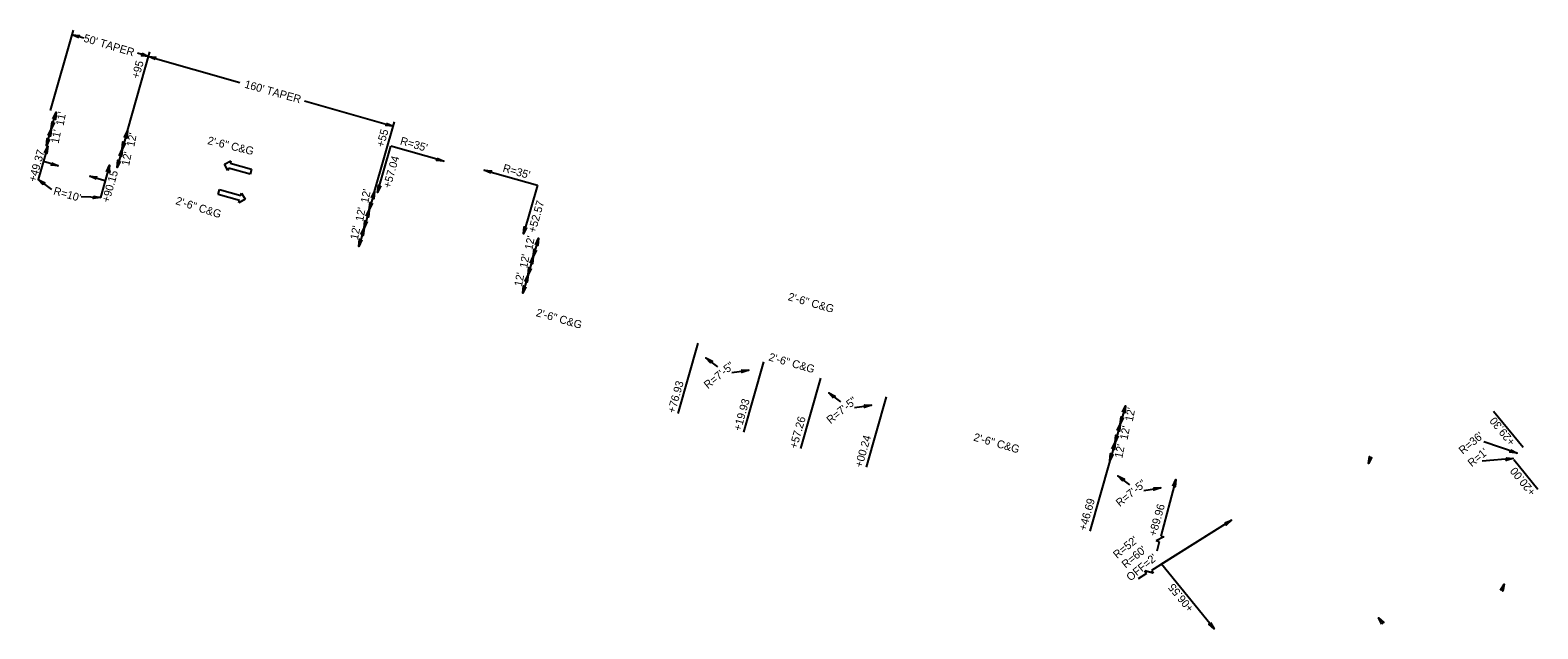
# Model space of a CAD drawing. Extents: x 2320991 to 2332664, y 598057 to 612602.
# Drawn here: x 2320991 to 2321940, y 598099 to 598475 of the extents above; entities that cross this region are included whole.
import ezdxf

# ---------------------------------------------------------------- set-up
doc = ezdxf.new("R2010")
doc.units = 0
for name, color, linetype in [('Prop Dimension', 7, 'Continuous'), ('Prop Dimension Text', 7, 'Continuous'), ('Prop Lane Arrow CELL', 7, 'Continuous'), ('Prop Terminator CELL', 7, 'Continuous')]:
    doc.layers.add(name, color=color, linetype=linetype)

msp = doc.modelspace()

# ---------------------------------------------------------------- linework, layer by layer
at = {"layer": 'Prop Dimension'}
for p, q in [((2321003.74, 598424.65), (2321018.17, 598475.28)), ((2321024.74, 598470.34), (2321017.37, 598472.44)), ((2321052.1, 598411.9), (2321066.26, 598461.58)), ((2321065.45, 598458.74), (2321058.32, 598460.77)), ((2321065.45, 598458.74), (2321122.9, 598442.36)), ((2321163.64, 598430.75), (2321219.32, 598414.87)), ((2321004.16, 598413.12), (2321007.18, 598423.7)), ((2321001.14, 598402.52), (2321004.15, 598413.09)), ((2321052.1, 598411.9), (2321048.81, 598400.36)), ((2321207.61, 598373.81), (2321220.13, 598417.71)), ((2321001.89, 598402.21), (2320995.93, 598381.3)), ((2321048.81, 598400.36), (2321045.52, 598388.82)), ((2321209.58, 598373.25), (2321217.88, 598402.37)), ((2321251.23, 598392.86), (2321217.88, 598402.37)), ((2321008.57, 598389.91), (2320999.15, 598392.6)), ((2321040.89, 598390.25), (2321035.12, 598370)), ((2320995.93, 598381.3), (2321004.19, 598375.07)), ((2321028.34, 598383.43), (2321038.15, 598380.63)), ((2321276.65, 598387.22), (2321310.17, 598377.66)), ((2321207.61, 598373.81), (2321204.33, 598362.27)), ((2321310.17, 598377.66), (2321301.45, 598347.06)), ((2321035.12, 598370), (2321023.02, 598370.34)), ((2321204.33, 598362.27), (2321201.04, 598350.73)), ((2321201.04, 598350.73), (2321197.75, 598339.19)), ((2321310.88, 598344.38), (2321307.59, 598332.84)), ((2321307.59, 598332.84), (2321304.3, 598321.3)), ((2321304.3, 598321.3), (2321301.01, 598309.75)), ((2321411.18, 598278.35), (2321398.57, 598234.11)), ((2321423.89, 598263.36), (2321416.33, 598269.08)), ((2321452.53, 598266.56), (2321439.92, 598222.32)), ((2321432.63, 598259.88), (2321443.26, 598261.41)), ((2321488.43, 598256.33), (2321475.82, 598212.09)), ((2321501.14, 598241.34), (2321493.58, 598247.06)), ((2321509.88, 598237.86), (2321520.51, 598239.39)), ((2321529.76, 598244.55), (2321517.15, 598200.31)), ((2321680.47, 598239.02), (2321677.18, 598227.48)), ((2321930.74, 598212.66), (2321912.13, 598235.45)), ((2321677.18, 598227.48), (2321673.89, 598215.94)), ((2321673.89, 598215.94), (2321670.6, 598204.4)), ((2321926.93, 598209.06), (2321906.05, 598216.36)), ((2321670.6, 598204.4), (2321657.99, 598160.16)), ((2321924.57, 598205.85), (2321905.07, 598204.03)), ((2321924.87, 598205.14), (2321940.05, 598186.55)), ((2321683.26, 598189.21), (2321675.7, 598194.93)), ((2321712.2, 598192.53), (2321702.66, 598156.92)), ((2321691.99, 598185.73), (2321702.63, 598187.26)), ((2321747.18, 598166.97), (2321696.71, 598135.39)), ((2321747.18, 598166.97), (2321702.69, 598139.13)), ((2321701.73, 598153.43), (2321700.11, 598147.38)), ((2321693.65, 598133.47), (2321688.34, 598130.15)), ((2321736.29, 598098.62), (2321703.04, 598139.35))]:
    msp.add_line(p, q, dxfattribs=at)
at = {"layer": 'Prop Dimension Text'}
for p, q in [((2321704.59, 598156.4), (2321699.79, 598153.95)), ((2321701.73, 598153.43), (2321699.79, 598153.95)), ((2321702.66, 598156.92), (2321704.59, 598156.4)), ((2321693.65, 598133.47), (2321692.58, 598135.17)), ((2321697.77, 598133.69), (2321692.58, 598135.17)), ((2321696.71, 598135.39), (2321697.77, 598133.69))]:
    msp.add_line(p, q, dxfattribs=at)
at = {"layer": 'Prop Lane Arrow CELL'}
for p, q in [((2321113.22, 598390.88), (2321117.13, 598393.1)), ((2321115.4, 598387.04), (2321113.22, 598390.88)), ((2321117.13, 598393.1), (2321116.72, 598391.65)), ((2321116.72, 598391.65), (2321130.18, 598387.82)), ((2321115.81, 598388.48), (2321115.4, 598387.04)), ((2321129.28, 598384.64), (2321115.81, 598388.48)), ((2321130.18, 598387.82), (2321129.28, 598384.64)), ((2321109.16, 598371.96), (2321110.07, 598375.14)), ((2321122.63, 598368.13), (2321109.16, 598371.96)), ((2321110.07, 598375.14), (2321123.53, 598371.3)), ((2321123.53, 598371.3), (2321123.94, 598372.74)), ((2321123.94, 598372.74), (2321126.12, 598368.9)), ((2321126.12, 598368.9), (2321122.22, 598366.68)), ((2321122.22, 598366.68), (2321122.63, 598368.13))]:
    msp.add_line(p, q, dxfattribs=at)
at = {"layer": 'Prop Terminator CELL'}
for points in [[(2321021.48, 598470.46), (2321017.37, 598472.44), (2321021.94, 598471.97), (2321021.16, 598471.36)], [(2321061.33, 598460.72), (2321065.45, 598458.74), (2321060.88, 598459.21), (2321061.65, 598459.82)], [(2321069.56, 598456.76), (2321065.45, 598458.74), (2321070.02, 598458.27), (2321069.25, 598457.65)], [(2321005.2, 598419.59), (2321007.18, 598423.7), (2321006.7, 598419.13), (2321006.09, 598419.9)], [(2321002.17, 598408.98), (2321004.15, 598413.09), (2321003.68, 598408.52), (2321003.07, 598409.3)], [(2321006.14, 598417.24), (2321004.16, 598413.12), (2321004.63, 598417.69), (2321005.24, 598416.92)], [(2321050.12, 598407.79), (2321052.1, 598411.9), (2321051.63, 598407.33), (2321051.02, 598408.11)], [(2321215.2, 598416.85), (2321219.32, 598414.87), (2321214.75, 598415.35), (2321215.52, 598415.96)], [(2320999.91, 598398.1), (2321001.89, 598402.21), (2321001.42, 598397.64), (2321000.8, 598398.41)], [(2321003.11, 598406.63), (2321001.14, 598402.52), (2321001.61, 598407.09), (2321002.22, 598406.31)], [(2321046.83, 598396.25), (2321048.81, 598400.36), (2321048.34, 598395.79), (2321047.73, 598396.57)], [(2321050.79, 598404.48), (2321048.81, 598400.36), (2321049.28, 598404.93), (2321049.89, 598404.16)], [(2321004.43, 598391.84), (2321008.57, 598389.91), (2321003.99, 598390.33), (2321004.76, 598390.95)], [(2321038.91, 598386.13), (2321040.89, 598390.25), (2321040.42, 598385.67), (2321039.8, 598386.45)], [(2321047.5, 598392.94), (2321045.52, 598388.82), (2321045.99, 598393.39), (2321046.6, 598392.62)], [(2321247.11, 598394.84), (2321251.23, 598392.86), (2321246.66, 598393.33), (2321247.43, 598393.94)], [(2320999.05, 598377.97), (2320995.93, 598381.3), (2321000.02, 598379.22), (2320999.08, 598378.92)], [(2321032.45, 598381.45), (2321028.34, 598383.43), (2321032.91, 598382.96), (2321032.13, 598382.34)], [(2321280.77, 598385.24), (2321276.65, 598387.22), (2321281.22, 598386.75), (2321280.45, 598386.14)], [(2321030.64, 598370.91), (2321035.12, 598370), (2321030.57, 598369.33), (2321031.17, 598370.12)], [(2321205.64, 598369.7), (2321207.61, 598373.81), (2321207.14, 598369.24), (2321206.53, 598370.01)], [(2321211.56, 598377.37), (2321209.58, 598373.25), (2321210.05, 598377.82), (2321210.66, 598377.05)], [(2321202.35, 598358.16), (2321204.33, 598362.27), (2321203.85, 598357.7), (2321203.24, 598358.47)], [(2321206.3, 598366.39), (2321204.33, 598362.27), (2321204.8, 598366.84), (2321205.41, 598366.07)], [(2321203.01, 598354.85), (2321201.04, 598350.73), (2321201.51, 598355.3), (2321202.12, 598354.53)], [(2321303.43, 598351.18), (2321301.45, 598347.06), (2321301.92, 598351.63), (2321302.53, 598350.86)], [(2321199.72, 598343.31), (2321197.75, 598339.19), (2321198.22, 598343.76), (2321198.83, 598342.99)], [(2321199.06, 598346.62), (2321201.04, 598350.73), (2321200.56, 598346.16), (2321199.95, 598346.93)], [(2321308.9, 598340.26), (2321310.88, 598344.38), (2321310.41, 598339.8), (2321309.8, 598340.58)], [(2321305.61, 598328.72), (2321307.59, 598332.84), (2321307.12, 598328.26), (2321306.51, 598329.04)], [(2321309.57, 598336.95), (2321307.59, 598332.84), (2321308.06, 598337.41), (2321308.67, 598336.63)], [(2321306.28, 598325.41), (2321304.3, 598321.3), (2321304.77, 598325.87), (2321305.38, 598325.09)], [(2321302.99, 598313.87), (2321301.01, 598309.75), (2321301.48, 598314.33), (2321302.09, 598313.55)], [(2321302.32, 598317.18), (2321304.3, 598321.3), (2321303.83, 598316.72), (2321303.22, 598317.5)], [(2321419.45, 598265.75), (2321416.33, 598269.08), (2321420.42, 598266.99), (2321419.48, 598266.7)], [(2321438.7, 598261.53), (2321443.26, 598261.41), (2321438.9, 598259.97), (2321439.35, 598260.84)], [(2321496.7, 598243.73), (2321493.58, 598247.06), (2321497.67, 598244.97), (2321496.73, 598244.68)], [(2321515.95, 598239.51), (2321520.51, 598239.39), (2321516.15, 598237.95), (2321516.6, 598238.82)], [(2321678.49, 598234.91), (2321680.47, 598239.02), (2321680, 598234.45), (2321679.39, 598235.22)], [(2321679.16, 598231.6), (2321677.18, 598227.48), (2321677.65, 598232.05), (2321678.26, 598231.28)], [(2321675.87, 598220.05), (2321673.89, 598215.94), (2321674.36, 598220.51), (2321674.98, 598219.74)], [(2321675.2, 598223.36), (2321677.18, 598227.48), (2321676.71, 598222.91), (2321676.1, 598223.68)], [(2321671.91, 598211.82), (2321673.89, 598215.94), (2321673.42, 598211.37), (2321672.81, 598212.14)], [(2321922.94, 598211.28), (2321926.93, 598209.06), (2321922.39, 598209.8), (2321923.2, 598210.36)], [(2321672.58, 598208.51), (2321670.6, 598204.4), (2321671.07, 598208.97), (2321671.69, 598208.2)], [(2321835.58, 598206.55), (2321833.36, 598202.56), (2321834.1, 598207.09), (2321834.66, 598206.29)], [(2321920.02, 598206.2), (2321924.57, 598205.85), (2321920.14, 598204.63), (2321920.63, 598205.48)], [(2321678.82, 598191.6), (2321675.7, 598194.93), (2321679.79, 598192.84), (2321678.85, 598192.55)], [(2321710.29, 598188.39), (2321712.2, 598192.53), (2321711.81, 598187.95), (2321711.18, 598188.72)], [(2321698.06, 598187.38), (2321702.63, 598187.26), (2321698.26, 598185.82), (2321698.72, 598186.69)], [(2321742.95, 598165.24), (2321747.18, 598166.97), (2321743.77, 598163.9), (2321743.83, 598164.88)], [(2321916.55, 598122.86), (2321918.88, 598126.79), (2321918.01, 598122.28), (2321917.47, 598123.1)], [(2321841.9, 598101.56), (2321839.65, 598105.54), (2321843.13, 598102.54), (2321842.15, 598102.48)], [(2321734.05, 598102.59), (2321736.29, 598098.62), (2321732.81, 598101.62), (2321733.8, 598101.68)]]:
    msp.add_lwpolyline(points, close=True, dxfattribs=at)

# ---------------------------------------------------------------- texts
at = {"layer": 'Prop Dimension'}
for s, p in [('+95', (2321059.32, 598444.37)), ('+55', (2321213.42, 598401.28)), ('+49.37', (2320994.41, 598379.4)), ('+90.15', (2321040.61, 598366.4))]:
    msp.add_text(s, height=5, rotation=74.08936, dxfattribs=at).set_placement(p)
at = {"layer": 'Prop Dimension Text'}
for s, rotation, p in [("50' TAPER", 343.36499, (2321024.08, 598468.16)), ("160' TAPER", 344.1391, (2321125.41, 598439.19)), ("11'", 78.96084, (2321011.84, 598414.83)), ("11'", 78.96084, (2321008.75, 598403.64)), ("12'", 78.96084, (2321056.38, 598401.59)), ('2\'-6" C&G', 346.23695, (2321102.15, 598403.69)), ("R=35'", 344.08936, (2321223.41, 598403.51)), ("12'", 78.96084, (2321053.17, 598389.68)), ('+57.04', 74.08936, (2321217.66, 598375.48)), ("R=35'", 344.08936, (2321288.01, 598386.4)), ("R=10'", 344.08936, (2321005.14, 598372.04)), ("12'", 78.96084, (2321203.72, 598366.2)), ('2\'-6" C&G', 342.35967, (2321082.03, 598365.91)), ("12'", 78.96084, (2321200.43, 598354.66)), ('+52.57', 74.08936, (2321308.95, 598347.37)), ("12'", 78.96084, (2321197.14, 598343.12)), ("12'", 78.96084, (2321306.99, 598336.77)), ("12'", 78.96084, (2321303.7, 598325.23)), ("12'", 78.96084, (2321300.41, 598313.69)), ('2\'-6" C&G', 344.10138, (2321467.6, 598305.48)), ('2\'-6" C&G', 344.10138, (2321308.94, 598295.46)), ('R=7\'-5"', 39.22799, (2321417.51, 598249.31)), ('2\'-6" C&G', 344.10138, (2321455.45, 598267.54)), ('+76.93', 74.08936, (2321396.72, 598233.94)), ('+19.93', 74.08936, (2321438.27, 598222.71)), ('R=7\'-5"', 39.22799, (2321494.75, 598227.29)), ("12'", 78.96084, (2321684.98, 598228.74)), ('+57.26', 74.08936, (2321473.52, 598211.58)), ('+29.30', 129.22799, (2321926.15, 598216.41)), ('+00.24', 74.08936, (2321514.66, 598199.73)), ('2\'-6" C&G', 344.10138, (2321584.37, 598217.11)), ("12'", 78.96084, (2321681.69, 598217.2)), ("R=36'", 39.22799, (2321892.76, 598208.12)), ("12'", 78.96084, (2321678.4, 598205.66)), ("R=1'", 39.22799, (2321898.42, 598200.21)), ('+20.00', 129.22799, (2321939.03, 598184.85)), ('R=7\'-5"', 39.22799, (2321676.87, 598175.16)), ('+46.69', 74.08936, (2321655.62, 598159.96)), ('+89.96', 74.08936, (2321699.7, 598156.51)), ("R=52'", 39.22799, (2321675.17, 598142.5)), ("R=60'", 39.22799, (2321680.56, 598136.41)), ("OFF=2'", 39.22799, (2321683.53, 598128.35)), ('+06.55', 129.22799, (2321723.81, 598111.65))]:
    msp.add_text(s, height=5, rotation=rotation, dxfattribs=at).set_placement(p)

doc.saveas('drawing.dxf')
